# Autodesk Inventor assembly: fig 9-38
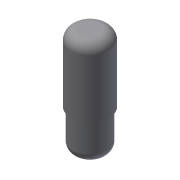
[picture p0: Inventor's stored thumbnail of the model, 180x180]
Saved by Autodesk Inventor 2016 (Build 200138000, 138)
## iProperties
Created: 2013-07
Part Number: fig 9-38
Document SubType Name: Assembly
Designer: CADCIM
Author: CADCIM
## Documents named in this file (3)
- D:\KAVITA\Autodesk Inventor_ 2016 Project_Kavita\Inventor_Part Files\Inventor_2016_Part\c09_Inv_2016\c09_inv_2016_prt\fig 9-38.iam
- D:\KAVITA\Autodesk Inventor_ 2016 Project_Kavita\Inventor_Part Files\Inventor_2016_Part\c09_Inv_2016\c09_inv_2016_prt\10.ipt
- D:\KAVITA\Autodesk Inventor_ 2016 Project_Kavita\Inventor_Part Files\Inventor_2016_Part\c09_Inv_2016\c09_inv_2016_prt\11.ipt
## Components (2 placed, 2 different names)
1. 10:1 — Rigid:1
2. 11:1 — Rigid:1
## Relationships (1: WeldJoint 1)
- Rigid:1 [WeldJoint]: 10:1 ↔ 11:1
